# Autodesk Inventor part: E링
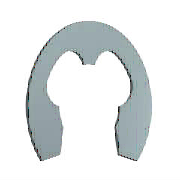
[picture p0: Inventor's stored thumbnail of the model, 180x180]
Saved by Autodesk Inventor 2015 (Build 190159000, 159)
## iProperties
Created: 2012-02
Part Number: E링
Material: 강철, 연강
Description: 스프링 리테이닝 링
Document SubType Name: Modeling
Standard: JIS B 2805
Designer: mduedu
Standards Organization: JIS
Language: ko-KR
Size Designation: 4
Categories: <MemberInstance><Categories><Category DisplayName="샤프트 부품" InternalName="7f7aeb1f-a693-4053-b835-cee3144e0d98" Mnemonic="SHFT"><Category DisplayName="써클립" Inter
Density: 1 g/cm^3
Appearance: 노란색
IsCustomPart: 1
Author: mduedu
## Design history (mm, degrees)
sketch "스케치1"
  geometry: L1 (-0.4, 0.024)-(0, 0.024) reference; L2 (-3.206, 0)-(3.486, 0) reference; L3 (-1.833, -3.276)-(1.833, -3.276); L4 (0, 1.949)-(0, -3.479) reference; L5 (-2.4, -1.676)-(-2.008, -1.676); L6 (-0.4, -0.076)-(-0.4, 0.312); L7 (0, 2.024)-(2.53, 2.024); L8 (-1.833, -3.276)-(-2.47, -5.119); L9 (0, -0.476)-(-1.278, -0.476); L10 (1.833, -3.276)-(2.47, -5.119); L11 (2.4, -1.676)-(2.008, -1.676); L12 (0.4, -0.076)-(0.4, 0.312); C1 r 2.5 at (0, -2.476); A1 r 2 centre (0, -2.476) between (-1.894, -1.835) and (-1.833, -3.276); A2 r 0.4 centre (0, -0.076) between (-0.4, -0.076) and (0.4, -0.076); A3 r 4.5 centre (0, -2.476) between (3.505, -5.299) and (-3.505, -5.299); A4 r 3.2 centre (0, -2.476) between (-0.8, 0.622) and (-2.824, -0.97); A5 r 0.32 centre (-0.72, 0.312) between (-0.4, 0.312) and (-0.8, 0.622); A6 r 0.48 centre (-2.4, -1.196) between (-2.824, -0.97) and (-2.4, -1.676); A7 r 0.12 centre (-2.008, -1.796) between (-1.894, -1.835) and (-2.008, -1.676); A8 r 0.6 centre (-3.037, -4.923) between (-3.505, -5.299) and (-2.47, -5.119); A9 r 0.6 centre (3.037, -4.923) between (2.47, -5.119) and (3.505, -5.299); A10 r 2 centre (0, -2.476) between (1.833, -3.276) and (1.894, -1.835); A11 r 0.12 centre (2.008, -1.796) between (2.008, -1.676) and (1.894, -1.835); A12 r 0.48 centre (2.4, -1.196) between (2.4, -1.676) and (2.824, -0.97); A13 r 3.2 centre (0, -2.476) between (2.824, -0.97) and (0.8, 0.622); A14 r 0.32 centre (0.72, 0.312) between (0.8, 0.622) and (0.4, 0.312); 1 further point
  constraints: 30 point on circle, 20 end point, 15 centre point, 13 symmetric about line, 12 tangent, 8 point on line, 4 parallel, 2 coincident, 2 horizontal, 1 concentric, 1 perpendicular, 1 vertical alignment, 9 other
  dimensions: "d0" = 5 diameter of C1 (= WD); "d3" = 0.8 distance from line of A1.centre L3 (= 0.2 x ND); "d4" = 0.4 radius of A2 (= 0.1 x ND); "d5" = 9 diameter of A3 (= SD2); "d8" = 3.2 radius of A4 (= 0.8 x ND); "d9" = 0.8 distance from line of A1.centre L5 (= 0.2 x ND); "d10" = 0.32 radius of A5 (= 0.08 x ND); "d11" = 0.48 radius of A6 (= 0.12 x ND); "d12" = 0.12 radius of A7 (= 0.03 x ND); "d13" = 0.6 radius of A8 (= 0.15 x ND); "d14" = 2 distance from line of A1.centre L9 (= 0.5 x ND); "d15" = 2 radius of A1 (= 0.5 x ND)
extrude "본체" new body sketch "스케치1" distance "d16" = 0.6 (= SD); taper "d17" = 0 deg
workaxis "Work Axis1"
workaxis "Work Axis2"
workplane "Work Plane1"
body "Solid1"
other parameters: "ND" = 4 [user parameter; used in 14 equation terms], "SD" = 0.6 [user parameter; used in 1 equation term], "WD" = 5 (= WDMIN) [user parameter; used in 1 equation term], "d1" = 6.4 (= 1.6 x ND), "d2" = 4 (= ND), "SD2" = 9 [user parameter; used in 1 equation term], "d6" = 4 (= ND), "d7" = 0.6 (= 0.15 x ND), "d18" = 0, "d19" = 0, "d27" = 0, "d28" = 0, "WDMIN" = 5 [user parameter; used in 1 equation term], "SNB" = 0.7 [user parameter], "WDMAX" = 7 [user parameter], "BUBRMI" = 1.2 [user parameter]
